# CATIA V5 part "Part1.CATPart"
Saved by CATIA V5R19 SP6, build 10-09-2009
Part number: Part1
Bounding box of the stored display mesh (mm): x 10 to 400, y 10 to 400, z -50 to 110
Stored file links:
  C:\Part1.CATPart
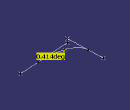
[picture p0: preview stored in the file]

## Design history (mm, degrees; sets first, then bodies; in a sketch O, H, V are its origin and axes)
AxisSystem1: origin (0, 0, 0), X (1, 0, 0), Y (0, 1, 0), Z (0, 0, 1)
StDynAnalysisRootNodeFeature1 "CATStDynAnalysisRootNodeName"
Set1
  Point1: (100, 400, 110), in AxisSystem1
  Point2: (10, 10, 10), in AxisSystem1
  Point3: (10, 10, -20), in AxisSystem1
  Point4: (400, 10, -50), in AxisSystem1
  Line1: type PtPt, FirstPoint Point2, SecondPoint Point1
  Line2: type PtPt, FirstPoint Point3, SecondPoint Point4
  Corner1: Element1 Line1, Element2 Line2, Radius 200, Direction (0, 0, 1)
  Point5: type OnCurve, Support Corner1, Ratio 0.5
  Circle1: type BitangentRad, Start 0, End 180, Radius 200, Element1 Line2, Element2 Point5
  Circle2: type BitangentRad, Start 0, End 180, Radius 200, Element1 Line1, Element2 Point5
Body1 (main body)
